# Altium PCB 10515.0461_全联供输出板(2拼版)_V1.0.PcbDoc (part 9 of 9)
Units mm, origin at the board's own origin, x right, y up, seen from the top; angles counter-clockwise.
Board outline 283.88 x 134.8 mm, 2 copper layers (Top Layer, Bottom Layer); 298 components, 0 nets, 1264 pads, 970 vias.
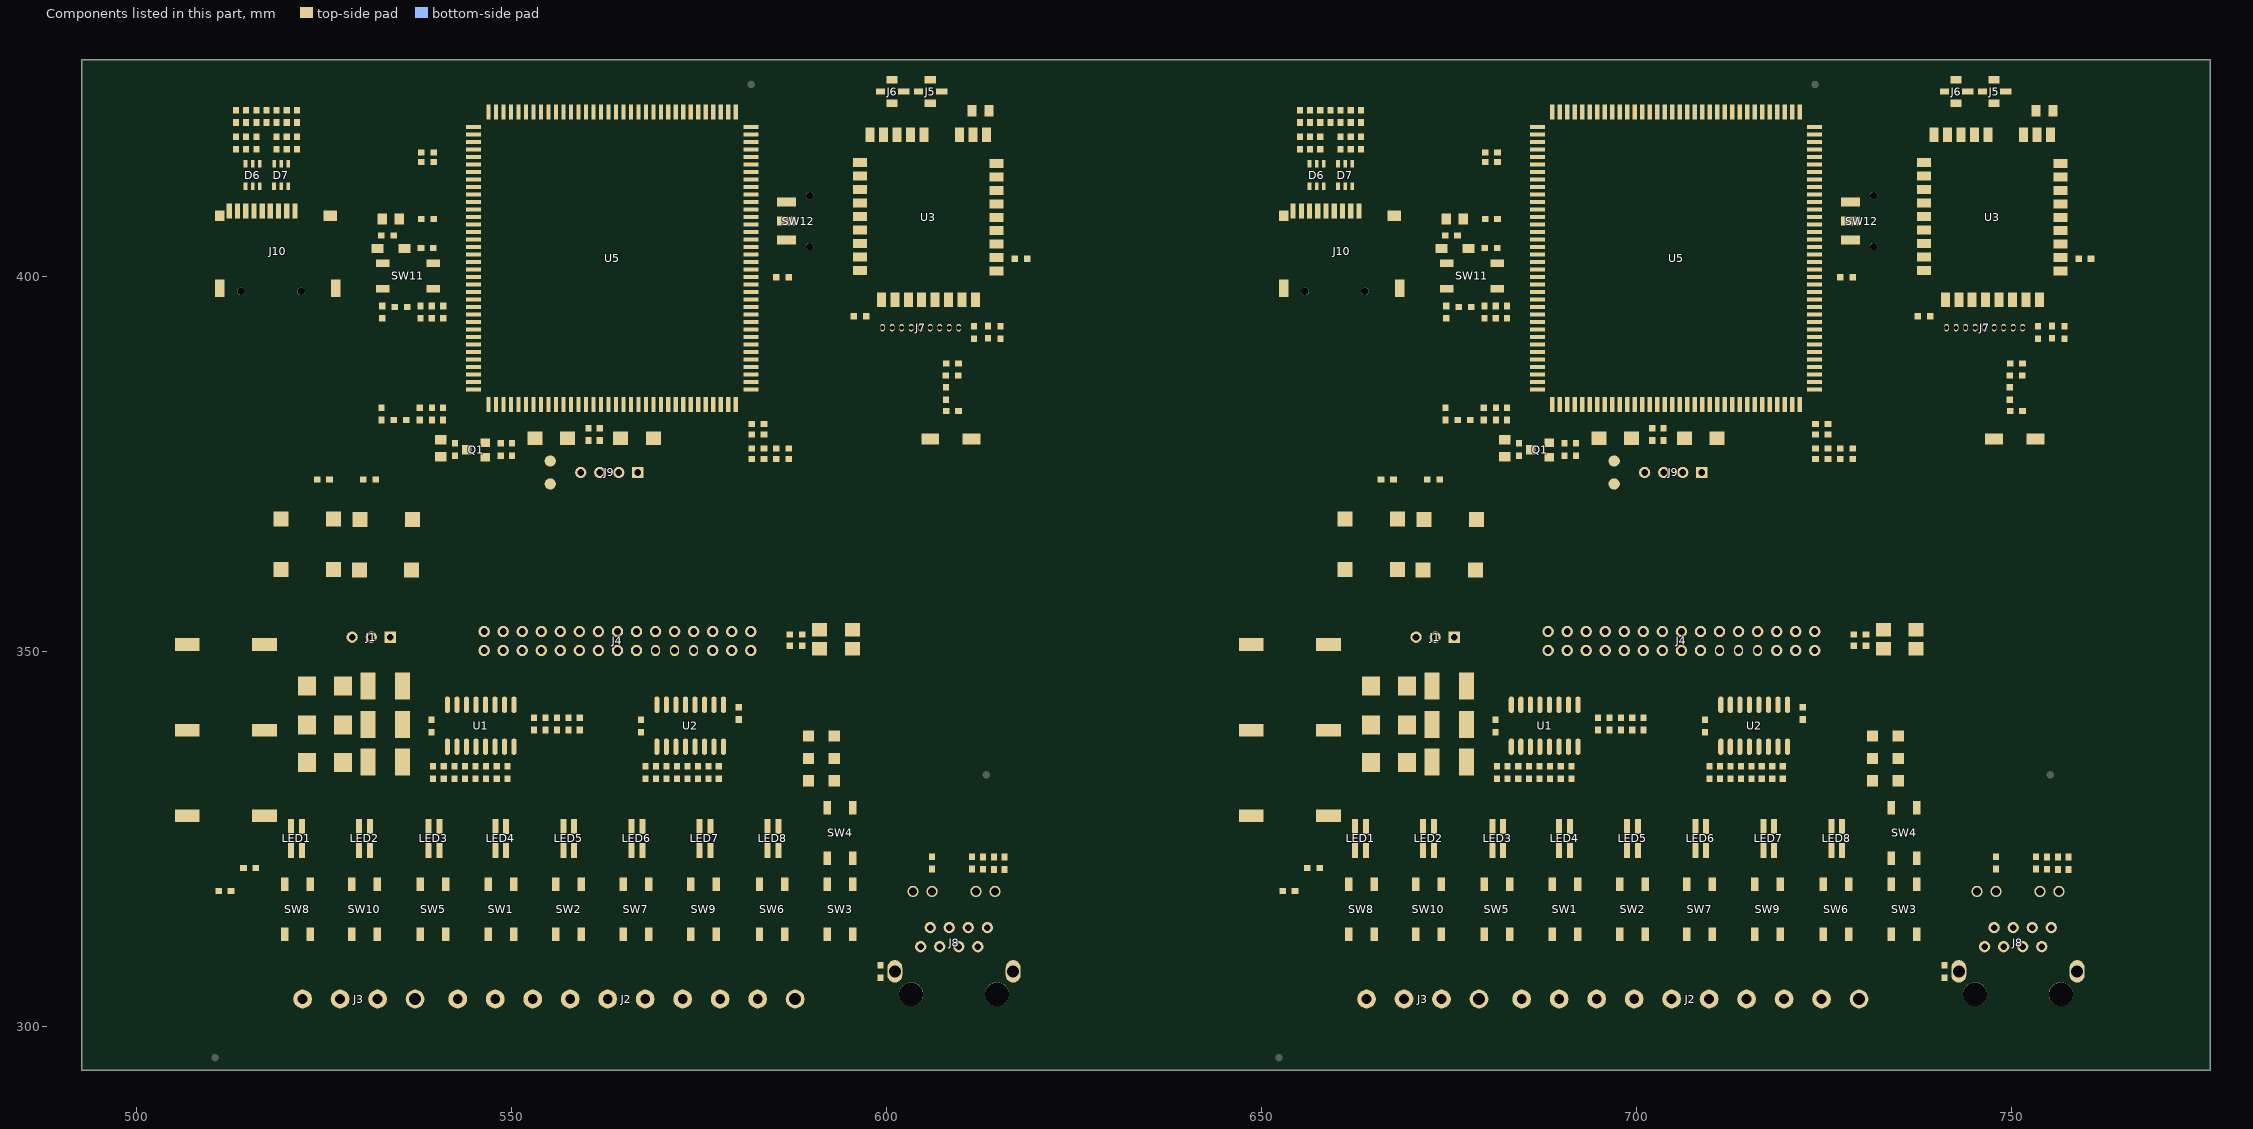
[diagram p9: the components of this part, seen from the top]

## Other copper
Top Layer:
  pour cut-out: 726.735,348.943 737.657,348.943 738.038,349.324 738.038,354.277 737.911,354.404 729.656,354.404 729.402,354.15 729.402,351.61
  pour cut-out: 713.781,345.768 716.321,345.768 716.575,345.514 716.575,342.974 716.194,342.593 713.527,342.593 713.4,342.72 713.4,345.387
  pour cut-out: 667.158,369.682 667.158,359.879 667.299,359.738 666.791,359.23 662.854,359.23 662.346,359.738 662.346,365.961 666.067,369.682
  pour cut-out: 672.76,368.755 672.76,359.331 673.141,358.95 675.834,358.95 677.205,357.579 677.205,366.469 675.046,368.628 672.887,368.628
  pour cut-out: 730.672,339.926 734.609,339.926 734.609,331.544 734.736,331.417 730.799,331.417 730.799,339.799
  pour cut-out: 675.902,347.038 677.299,345.641 677.299,334.752 678.475,333.576 680.761,333.576 680.761,331.255 677.113,327.607 661.203,327.607 660.441,328.369 660.441,333.068 660.695,333.322 657.012,333.322 656.631,333.703 656.631,349.578 658.409,351.356 658.409,351.229 662.6,347.038
  pour cut-out: 661.076,320.368 665.394,320.368 665.521,320.241 665.521,313.64 666.918,312.243 668.699,312.243 669.839,313.383 674.411,313.383 674.411,309.446 674.157,309.192 662.6,309.192 661.33,310.462 661.33,320.114
  pour cut-out: 695.62,357.198 695.62,350.086 696.509,349.197 713.654,349.197 714.416,349.959 714.416,355.674 713.019,357.071 695.874,357.071
  pour cut-out: 669.458,322.654 669.458,312.494 669.712,312.24 674.284,312.24 674.665,312.621 674.665,322.146 674.157,322.654
  pour cut-out: 736.133,426.794 736.133,393.774 736.387,393.52 757.723,393.52 758.612,394.409 758.612,427.302 757.088,427.048 736.26,427.048
  pour cut-out: 744.769,322.4 757.088,322.4 758.358,321.13 758.358,318.209 755.818,315.669 755.818,310.843 754.802,309.827 754.294,310.335 746.166,310.335 745.404,311.097 745.404,316.939 744.769,317.574
  pour cut-out: 690.032,346.022 690.032,343.468 692.328,341.173 702.455,341.173 703.113,341.831 703.113,349.451 702.859,349.705 696.763,349.705 693.08,346.022
  pour cut-out: 681.015,349.07 681.65,349.705 695.112,349.705 695.112,348.054 694.223,347.165 681.142,347.165 680.761,346.784 680.761,349.324 681.015,349.578
  pour cut-out: 733.593,348.816 736.26,348.816 736.133,354.023 733.339,354.023 733.466,348.943
  pour cut-out: 693.334,381.582 701.97,381.582 702.224,381.328 702.224,379.931 701.843,379.55 698.795,379.55 698.287,379.042 698.922,378.407 698.922,376.121 698.668,375.867 696.509,375.867 695.366,377.01 695.366,379.144 694.96,379.55 693.461,379.55 693.334,379.677
  pour cut-out: 584.835,348.943 595.757,348.943 596.138,349.324 596.138,354.277 596.011,354.404 587.756,354.404 587.502,354.15 587.502,351.61
  pour cut-out: 571.881,345.768 574.421,345.768 574.675,345.514 574.675,342.974 574.294,342.593 571.627,342.593 571.5,342.72 571.5,345.387
  pour cut-out: 525.258,369.682 525.258,359.879 525.399,359.738 524.891,359.23 520.954,359.23 520.446,359.738 520.446,365.961 524.167,369.682
  pour cut-out: 530.86,368.755 530.86,359.331 531.241,358.95 533.934,358.95 535.305,357.579 535.305,366.469 533.146,368.628 530.987,368.628
  pour cut-out: 588.772,339.926 592.709,339.926 592.709,331.544 592.836,331.417 588.899,331.417 588.899,339.799
  pour cut-out: 534.002,347.038 535.399,345.641 535.399,334.752 536.575,333.576 538.861,333.576 538.861,331.255 535.213,327.607 519.303,327.607 518.541,328.369 518.541,333.068 518.795,333.322 515.112,333.322 514.731,333.703 514.731,349.578 516.509,351.356 516.509,351.229 520.7,347.038
  pour cut-out: 519.176,320.368 523.494,320.368 523.621,320.241 523.621,313.64 525.018,312.243 526.799,312.243 527.939,313.383 532.511,313.383 532.511,309.446 532.257,309.192 520.7,309.192 519.43,310.462 519.43,320.114
  pour cut-out: 553.72,357.198 553.72,350.086 554.609,349.197 571.754,349.197 572.516,349.959 572.516,355.674 571.119,357.071 553.974,357.071
  pour cut-out: 527.558,322.654 527.558,312.494 527.812,312.24 532.384,312.24 532.765,312.621 532.765,322.146 532.257,322.654
  pour cut-out: 594.233,426.794 594.233,393.774 594.487,393.52 615.823,393.52 616.712,394.409 616.712,427.302 615.188,427.048 594.36,427.048
  pour cut-out: 602.869,322.4 615.188,322.4 616.458,321.13 616.458,318.209 613.918,315.669 613.918,310.843 612.902,309.827 612.394,310.335 604.266,310.335 603.504,311.097 603.504,316.939 602.869,317.574
  pour cut-out: 548.132,346.022 548.132,343.468 550.428,341.173 560.555,341.173 561.213,341.831 561.213,349.451 560.959,349.705 554.863,349.705 551.18,346.022
  pour cut-out: 539.115,349.07 539.75,349.705 553.212,349.705 553.212,348.054 552.323,347.165 539.242,347.165 538.861,346.784 538.861,349.324 539.115,349.578
  pour cut-out: 591.693,348.816 594.36,348.816 594.233,354.023 591.439,354.023 591.566,348.943
  pour cut-out: 551.434,381.582 560.07,381.582 560.324,381.328 560.324,379.931 559.943,379.55 556.895,379.55 556.387,379.042 557.022,378.407 557.022,376.121 556.768,375.867 554.609,375.867 553.466,377.01 553.466,379.144 553.06,379.55 551.561,379.55 551.434,379.677
Bottom Layer:
  pour cut-out: 688,349.07 710.685,349.07 711.066,349.451 711.066,353.817 710.86,354.023 692.953,354.023
  pour cut-out: 669.966,308.811 668.696,307.541 668.696,301.953 673.649,301.953 673.776,302.08 673.776,308.557 673.522,308.811
  pour cut-out: 753.532,320.368 754.675,319.225 756.707,319.225 756.707,311.605 754.548,309.446 746.166,309.446 746.166,311.097 747.944,312.875 750.992,312.875 752.389,314.272 752.389,319.225
  pour cut-out: 685.079,345.26 688.254,345.26 689.016,346.022 689.016,344.117 688.381,343.482 685.714,343.482 685.079,344.117
  pour cut-out: 718.226,340.053 724.703,340.053 725.465,340.815 725.465,345.133 724.449,346.149 719.623,346.149 717.972,344.498 717.972,340.307
  pour cut-out: 546.1,349.07 568.785,349.07 569.166,349.451 569.166,353.817 568.96,354.023 551.053,354.023
  pour cut-out: 528.066,308.811 526.796,307.541 526.796,301.953 531.749,301.953 531.876,302.08 531.876,308.557 531.622,308.811
  pour cut-out: 611.632,320.368 612.775,319.225 614.807,319.225 614.807,311.605 612.648,309.446 604.266,309.446 604.266,311.097 606.044,312.875 609.092,312.875 610.489,314.272 610.489,319.225
  pour cut-out: 543.179,345.26 546.354,345.26 547.116,346.022 547.116,344.117 546.481,343.482 543.814,343.482 543.179,344.117
  pour cut-out: 576.326,340.053 582.803,340.053 583.565,340.815 583.565,345.133 582.549,346.149 577.723,346.149 576.072,344.498 576.072,340.307

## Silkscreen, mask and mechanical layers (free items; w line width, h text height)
Top Overlay:
  lines w0.127: 562.263,297.116 562.263,295.846 563.279,295.846 ; 563.914,294.703 566.136,296.925 ; 565.819,296.862 565.882,296.925 566.136,296.925 ; 566.073,296.608 566.136,296.671 566.136,296.925 ; 566.835,295.846 567.978,295.846 567.978,297.116 ; 572.169,297.116 572.169,295.846 573.185,295.846 ; 573.82,294.703 576.042,296.925 ; 575.725,296.862 575.788,296.925 576.042,296.925 ; 575.979,296.608 576.042,296.671 576.042,296.925 ; 576.741,295.846 577.884,295.846 577.884,297.116 ; 582.329,297.116 582.329,295.846 583.345,295.846 ; 583.98,294.703 586.202,296.925 ; 585.885,296.862 585.948,296.925 586.202,296.925 ; 586.139,296.608 586.202,296.671 586.202,296.925 ; 586.901,295.846 588.044,295.846 588.044,297.116 ; 704.163,297.116 704.163,295.846 705.179,295.846 ; 705.814,294.703 708.036,296.925 ; 707.719,296.862 707.782,296.925 708.036,296.925 ; 707.973,296.608 708.036,296.671 708.036,296.925 ; 708.735,295.846 709.878,295.846 709.878,297.116 ; 714.069,297.116 714.069,295.846 715.085,295.846 ; 715.72,294.703 717.942,296.925 ; 717.625,296.862 717.688,296.925 717.942,296.925 ; 717.879,296.608 717.942,296.671 717.942,296.925 ; 718.641,295.846 719.784,295.846 719.784,297.116 ; 724.229,297.116 724.229,295.846 725.245,295.846 ; 725.88,294.703 728.102,296.925 ; 727.785,296.862 727.848,296.925 728.102,296.925 ; 728.039,296.608 728.102,296.671 728.102,296.925 ; 728.801,295.846 729.944,295.846 729.944,297.116 ; 563.279,295.846 563.279,295.211 566.835,295.211 566.835,296.354 563.279,296.354 563.279,295.846 ; 573.185,295.846 573.185,296.354 576.741,296.354 576.741,295.211 573.185,295.211 573.185,295.846 ; 583.345,295.846 583.345,296.354 586.901,296.354 586.901,295.211 583.345,295.211 583.345,295.846 ; 705.179,295.846 705.179,295.211 708.735,295.211 708.735,296.354 705.179,296.354 705.179,295.846 ; 715.085,295.846 715.085,296.354 718.641,296.354 718.641,295.211 715.085,295.211 715.085,295.846 ; 725.245,295.846 725.245,296.354 728.801,296.354 728.801,295.211 725.245,295.211 725.245,295.846
  text "10515.0461_全联供输出板_V1.0" at 547.624,426.212 h2.5
  text "10515.0461_全联供输出板_V1.0" at 689.524,426.212 h2.5
  text "20200526H1.6Sn" at 550.545,423.672 h2.5
  text "20200526H1.6Sn" at 692.445,423.672 h2.5
  text "SD" at 592.328,410.919 h1.5
  text "SD" at 734.228,410.919 h1.5
  text "NANO" at 590.423,401.14 h1.5
  text "NANO" at 732.323,401.14 h1.5
  text "+24V" at 525.399,355.219 h2
  text "UART" at 529.971,355.219 h2
  text "+24V" at 667.299,355.219 h2
  text "UART" at 671.871,355.219 h2
  text "GND" at 535.051,355.166 h2
  text "GND" at 676.951,355.166 h2
  text "单线通讯" at 518.287,351.663 h2
  text "单线通讯" at 660.187,351.663 h2
  text "A2" at 546.608,296.037 h2
  text "A2" at 688.508,296.037 h2
  text "GND" at 556.167,295.994 h2
  text "GND" at 698.067,295.994 h2
  text "B2" at 551.976,295.973 h2
  text "B2" at 693.876,295.973 h2
  text "0-10V" at 524.891,295.933 h2
  text "0-10V" at 666.791,295.933 h2
  text "+24V" at 540.512,295.91 h2
  text "+24V" at 682.412,295.91 h2
  text "反馈端" at 530.225,295.73 h2
  text "反馈端" at 672.125,295.73 h2
  text "+24V" at 519.684,295.603 h2
  text "+24V" at 661.584,295.603 h2
  text "GND" at 535.94,295.529 h2
  text "GND" at 677.84,295.529 h2
  text "RS485" at 547.751,294.46 h2
  text "RS485" at 689.651,294.46 h2
  text "输出端" at 524.51,294.386 h2
  text "输出端" at 666.41,294.386 h2
Bottom Overlay:
  lines w0.127: 503.125,294.079 503.125,428.879 ; 624.125,294.079 624.125,428.879 ; 645.025,294.079 645.025,428.879 ; 766.025,294.079 766.025,428.879
Mechanical 8:
  drawing of 280 lines, arcs and shapes, not listed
